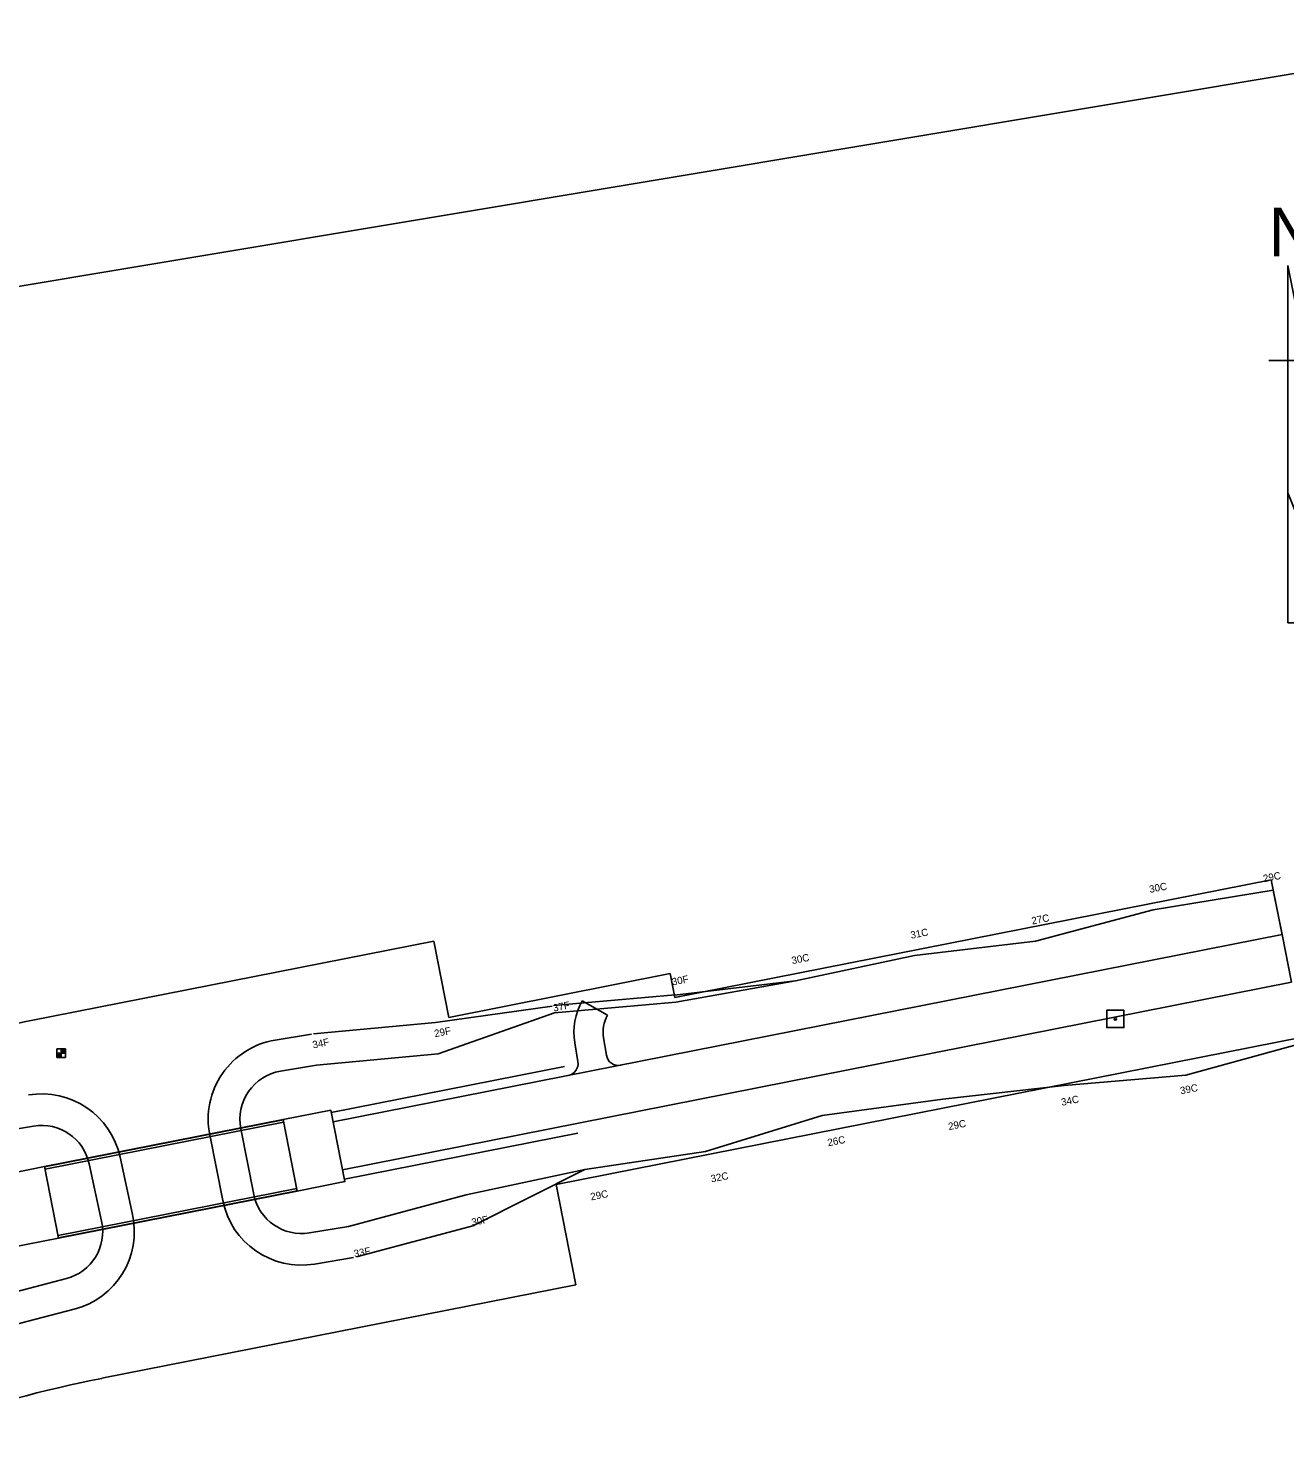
# Model space of a CAD drawing. Extents: x 1509010 to 1513406, y 898655 to 900162.
# Drawn here: x 1510966 to 1511482, y 899577 to 900162 of the extents above; entities that cross this region are included whole.
import ezdxf

# ---------------------------------------------------------------- set-up
doc = ezdxf.new("R2010")
doc.units = 0
for name, color, linetype in [('BR_CONCRETE', 7, 'Continuous'), ('RD_EX_Misc', 7, 'Continuous'), ('RD_HC_Survey', 7, 'Continuous'), ('RD_PD_CstnLmt', 7, 'Continuous'), ('RD_PD_CstnLmt_TX', 7, 'Continuous'), ('RD_PD_DR_ErosCtrl', 7, 'Continuous'), ('RD_PD_Final_TrvlWay', 7, 'Continuous'), ('RD_PD_GR', 7, 'Continuous'), ('RD_PD_RW', 7, 'Continuous'), ('RD_Sketch2', 7, 'Continuous')]:
    doc.layers.add(name, color=color, linetype=linetype)

# ---------------------------------------------------------------- blocks, each defined once
blk = doc.blocks.new('NA')
at = {"layer": 'RD_EX_Misc'}
for p, q in [((7.92, 31.07), (0.08, 70.27)), ((0.08, 70.27), (0.08, 70.27)), ((0.08, 70.27), (0.08, 31.07)), ((-7.76, 31.07), (0.08, 31.07)), ((0.08, -23.33), (0.08, 31.07)), ((0.08, 31.07), (7.92, 31.07)), ((7.92, 31.07), (7.92, 31.54)), ((9.88, -47.33), (0.08, -23.33)), ((0.08, -23.33), (0.08, -76.73)), ((9.88, -76.73), (9.88, -47.06)), ((9.88, -47.06), (9.88, -47.33)), ((0.08, -76.73), (9.88, -76.73))]:
    blk.add_line(p, q, dxfattribs=at)
blk.add_text('N', height=20, dxfattribs=at).set_placement((-7.81, 73.98))

msp = doc.modelspace()

# ---------------------------------------------------------------- linework, layer by layer
at = {"layer": 'BR_CONCRETE'}
for p, q in [((1510972.26, 899694.11), (1511070.36, 899713.48)), ((1510972.45, 899693.13), (1511070.55, 899712.5)), ((1510977.84, 899665.82), (1511075.95, 899685.2)), ((1510978.03, 899664.84), (1511076.14, 899684.22))]:
    msp.add_line(p, q, dxfattribs=at)
for points in [[(1510972.24, 899694.19), (1511070.34, 899713.57), (1511076.16, 899684.13), (1510978.05, 899664.76)], [(1511089.97, 899717.44), (1511070.34, 899713.57), (1511076.16, 899684.13), (1511095.78, 899688.01)], [(1510972.24, 899694.19), (1510952.62, 899690.32), (1510958.43, 899660.89), (1510978.05, 899664.76)]]:
    msp.add_lwpolyline(points, close=True, dxfattribs=at)
at = {"layer": 'RD_HC_Survey'}
for p, q in [((1510979.06, 899742.59), (1510979.06, 899739.09)), ((1510979.08, 899742.59), (1510979.08, 899740.84)), ((1510979.1, 899742.59), (1510979.1, 899740.84)), ((1510979.13, 899742.59), (1510979.13, 899740.84)), ((1510979.15, 899742.59), (1510979.15, 899740.84)), ((1510979.17, 899742.59), (1510979.17, 899740.84)), ((1510979.2, 899742.59), (1510979.2, 899740.84)), ((1510979.22, 899742.59), (1510979.22, 899740.84)), ((1510979.25, 899742.59), (1510979.25, 899740.84)), ((1510979.27, 899742.59), (1510979.27, 899740.84)), ((1510979.3, 899742.59), (1510979.3, 899740.84)), ((1510979.32, 899742.59), (1510979.32, 899740.84)), ((1510979.35, 899742.59), (1510979.35, 899740.84)), ((1510979.37, 899742.59), (1510979.37, 899740.84)), ((1510979.4, 899742.59), (1510979.4, 899740.84)), ((1510979.42, 899742.59), (1510979.42, 899740.84)), ((1510979.45, 899742.59), (1510979.45, 899740.84)), ((1510979.47, 899742.59), (1510979.47, 899740.84)), ((1510979.5, 899742.59), (1510979.5, 899740.84)), ((1510979.52, 899742.59), (1510979.52, 899740.84)), ((1510979.55, 899742.59), (1510979.55, 899740.84)), ((1510979.57, 899742.59), (1510979.57, 899740.84)), ((1510979.6, 899742.59), (1510979.6, 899740.84)), ((1510979.62, 899742.59), (1510979.62, 899740.84)), ((1510979.64, 899742.59), (1510979.64, 899740.84)), ((1510979.67, 899742.59), (1510979.67, 899740.84)), ((1510979.69, 899742.59), (1510979.69, 899740.84)), ((1510979.72, 899742.59), (1510979.72, 899740.84)), ((1510979.74, 899742.59), (1510979.74, 899740.84)), ((1510979.77, 899742.59), (1510979.77, 899740.84)), ((1510979.79, 899742.59), (1510979.79, 899740.84)), ((1510979.82, 899742.59), (1510979.82, 899740.84)), ((1510979.84, 899742.59), (1510979.84, 899740.84)), ((1510979.87, 899742.59), (1510979.87, 899740.84)), ((1510979.89, 899742.59), (1510979.89, 899740.84)), ((1510979.92, 899742.59), (1510979.92, 899740.84)), ((1510979.94, 899742.59), (1510979.94, 899740.84)), ((1510979.97, 899742.59), (1510979.97, 899740.84)), ((1510979.99, 899742.59), (1510979.99, 899740.84)), ((1510980.02, 899742.59), (1510980.02, 899740.84)), ((1510980.04, 899742.59), (1510980.04, 899740.84)), ((1510980.07, 899742.59), (1510980.07, 899740.84)), ((1510980.09, 899742.59), (1510980.09, 899740.84)), ((1510980.12, 899742.59), (1510980.12, 899740.84)), ((1510980.14, 899742.59), (1510980.14, 899740.84)), ((1510980.16, 899742.59), (1510980.16, 899740.84)), ((1510980.19, 899742.59), (1510980.19, 899740.84)), ((1510980.21, 899742.59), (1510980.21, 899740.84)), ((1510980.24, 899742.59), (1510980.24, 899740.84)), ((1510980.26, 899742.59), (1510980.26, 899740.84)), ((1510980.29, 899742.59), (1510980.29, 899740.84)), ((1510980.31, 899742.59), (1510980.31, 899740.84)), ((1510980.34, 899742.59), (1510980.34, 899740.84)), ((1510980.36, 899742.59), (1510980.36, 899740.84)), ((1510980.39, 899742.59), (1510980.39, 899740.84)), ((1510980.41, 899742.59), (1510980.41, 899740.84)), ((1510980.44, 899742.59), (1510980.44, 899740.84)), ((1510980.46, 899742.59), (1510980.46, 899740.84)), ((1510980.49, 899742.59), (1510980.49, 899740.84)), ((1510980.51, 899742.59), (1510980.51, 899740.84)), ((1510980.54, 899742.59), (1510980.54, 899740.84)), ((1510980.56, 899742.59), (1510980.56, 899740.84)), ((1510980.59, 899742.59), (1510980.59, 899740.84)), ((1510980.61, 899742.59), (1510980.61, 899740.84)), ((1510980.63, 899742.59), (1510980.63, 899740.84)), ((1510980.66, 899742.59), (1510980.66, 899740.84)), ((1510980.68, 899742.59), (1510980.68, 899740.84)), ((1510980.71, 899742.59), (1510980.71, 899740.84)), ((1510980.73, 899742.59), (1510980.73, 899740.84)), ((1510980.76, 899742.59), (1510980.76, 899740.84)), ((1510980.78, 899742.59), (1510980.78, 899740.84)), ((1510980.81, 899740.84), (1510977.31, 899740.84)), ((1510977.31, 899740.84), (1510977.31, 899739.09)), ((1510977.33, 899740.84), (1510977.33, 899739.09)), ((1510977.36, 899740.84), (1510977.36, 899739.09)), ((1510977.38, 899740.84), (1510977.38, 899739.09)), ((1510977.41, 899740.84), (1510977.41, 899739.09)), ((1510977.43, 899740.84), (1510977.43, 899739.09)), ((1510977.46, 899740.84), (1510977.46, 899739.09)), ((1510977.48, 899740.84), (1510977.48, 899739.09)), ((1510977.51, 899740.84), (1510977.51, 899739.09)), ((1510977.53, 899740.84), (1510977.53, 899739.09)), ((1510977.56, 899740.84), (1510977.56, 899739.09)), ((1510977.58, 899740.84), (1510977.58, 899739.09)), ((1510977.6, 899740.84), (1510977.6, 899739.09)), ((1510977.63, 899740.84), (1510977.63, 899739.09)), ((1510977.65, 899740.84), (1510977.65, 899739.09)), ((1510977.68, 899740.84), (1510977.68, 899739.09)), ((1510977.7, 899740.84), (1510977.7, 899739.09)), ((1510977.73, 899740.84), (1510977.73, 899739.09)), ((1510977.75, 899740.84), (1510977.75, 899739.09)), ((1510977.78, 899740.84), (1510977.78, 899739.09)), ((1510977.8, 899740.84), (1510977.8, 899739.09)), ((1510977.83, 899740.84), (1510977.83, 899739.09)), ((1510977.85, 899740.84), (1510977.85, 899739.09)), ((1510977.88, 899740.84), (1510977.88, 899739.09)), ((1510977.9, 899740.84), (1510977.9, 899739.09)), ((1510977.93, 899740.84), (1510977.93, 899739.09)), ((1510977.95, 899740.84), (1510977.95, 899739.09)), ((1510977.98, 899740.84), (1510977.98, 899739.09)), ((1510978, 899740.84), (1510978, 899739.09)), ((1510978.03, 899740.84), (1510978.03, 899739.09)), ((1510978.05, 899740.84), (1510978.05, 899739.09)), ((1510978.08, 899740.84), (1510978.08, 899739.09)), ((1510978.1, 899740.84), (1510978.1, 899739.09)), ((1510978.12, 899740.84), (1510978.12, 899739.09)), ((1510978.15, 899740.84), (1510978.15, 899739.09)), ((1510978.17, 899740.84), (1510978.17, 899739.09)), ((1510978.2, 899740.84), (1510978.2, 899739.09)), ((1510978.22, 899740.84), (1510978.22, 899739.09)), ((1510978.25, 899740.84), (1510978.25, 899739.09)), ((1510978.27, 899740.84), (1510978.27, 899739.09)), ((1510978.3, 899740.84), (1510978.3, 899739.09)), ((1510978.32, 899740.84), (1510978.32, 899739.09)), ((1510978.35, 899740.84), (1510978.35, 899739.09)), ((1510978.37, 899740.84), (1510978.37, 899739.09)), ((1510978.4, 899740.84), (1510978.4, 899739.09)), ((1510978.42, 899740.84), (1510978.42, 899739.09)), ((1510978.45, 899740.84), (1510978.45, 899739.09)), ((1510978.47, 899740.84), (1510978.47, 899739.09)), ((1510978.5, 899740.84), (1510978.5, 899739.09)), ((1510978.52, 899740.84), (1510978.52, 899739.09)), ((1510978.55, 899740.84), (1510978.55, 899739.09)), ((1510978.57, 899740.84), (1510978.57, 899739.09)), ((1510978.59, 899740.84), (1510978.59, 899739.09)), ((1510978.62, 899740.84), (1510978.62, 899739.09)), ((1510978.64, 899740.84), (1510978.64, 899739.09)), ((1510978.67, 899740.84), (1510978.67, 899739.09)), ((1510978.69, 899740.84), (1510978.69, 899739.09)), ((1510978.72, 899740.84), (1510978.72, 899739.09)), ((1510978.74, 899740.84), (1510978.74, 899739.09)), ((1510978.77, 899740.84), (1510978.77, 899739.09)), ((1510978.79, 899740.84), (1510978.79, 899739.09)), ((1510978.82, 899740.84), (1510978.82, 899739.09)), ((1510978.84, 899740.84), (1510978.84, 899739.09)), ((1510978.87, 899740.84), (1510978.87, 899739.09)), ((1510978.89, 899740.84), (1510978.89, 899739.09)), ((1510978.92, 899740.84), (1510978.92, 899739.09)), ((1510978.94, 899740.84), (1510978.94, 899739.09)), ((1510978.97, 899740.84), (1510978.97, 899739.09)), ((1510978.99, 899740.84), (1510978.99, 899739.09)), ((1510979.02, 899740.84), (1510979.02, 899739.09)), ((1510979.04, 899740.84), (1510979.04, 899739.09))]:
    msp.add_line(p, q, dxfattribs=at)
for points in [[(1511416.18, 899758.46), (1511409.11, 899758.46), (1511409.11, 899751.39), (1511416.18, 899751.39)], [(1510980.81, 899742.59), (1510977.31, 899742.59), (1510977.31, 899739.09), (1510980.81, 899739.09)]]:
    msp.add_lwpolyline(points, close=True, dxfattribs=at)
msp.add_circle((1511412.65, 899754.92), 0.5, dxfattribs=at)
at = {"layer": 'RD_PD_CstnLmt'}
for p, q in [((1511428.26, 899799.86), (1511477.62, 899807.95)), ((1511477.62, 899807.95), (1511481.25, 899789.61)), ((1511379.86, 899786.86), (1511428.26, 899799.86)), ((1511330.05, 899780.99), (1511379.86, 899786.86)), ((1511281.15, 899770.56), (1511330.05, 899780.99)), ((1511231.92, 899761.78), (1511281.15, 899770.56)), ((1511182.01, 899757.41), (1511231.92, 899761.78)), ((1511134.18, 899740.52), (1511182.01, 899757.41)), ((1511441.69, 899731.84), (1511490.03, 899745.13)), ((1511084.13, 899735.89), (1511069.25, 899733.41)), ((1511084.13, 899735.89), (1511134.18, 899740.52)), ((1511391.59, 899727.48), (1511441.69, 899731.84)), ((1511341.72, 899721.92), (1511391.59, 899727.48)), ((1511292.06, 899715.27), (1511341.72, 899721.92)), ((1511244.03, 899700.41), (1511292.06, 899715.27)), ((1510935.04, 899705.37), (1510967.77, 899710.83)), ((1511058.29, 899682.77), (1511052.93, 899709.79)), ((1511194.53, 899693), (1511244.03, 899700.41)), ((1510995.72, 899671.7), (1510990.61, 899695.33)), ((1511145.63, 899682.52), (1511194.53, 899693)), ((1511097.22, 899669.61), (1511145.63, 899682.52)), ((1511097.22, 899669.61), (1511081.2, 899666.93)), ((1510952.21, 899640.58), (1510981.21, 899648.12))]:
    msp.add_line(p, q, dxfattribs=at)
for centre, start, end in [((1511072.55, 899713.68), 99.47431, 191.2324), ((1510971.06, 899691.1), 12.18941, 99.47431), ((1511077.91, 899686.66), 191.2324, 279.47431), ((1510976.17, 899667.48), 284.5933, 12.18941)]:
    msp.add_arc(centre, 20, start, end, dxfattribs=at)
at = {"layer": 'RD_PD_DR_ErosCtrl'}
for p, q in [((1511231.33, 899764.72), (1511281.15, 899770.56)), ((1511181.75, 899760.4), (1511231.65, 899764.77)), ((1511132.99, 899753.46), (1511181.01, 899760.24)), ((1511082.93, 899748.84), (1511132.99, 899753.46)), ((1511081.99, 899748.72), (1511067.11, 899746.23)), ((1511045.54, 899680.23), (1511040.18, 899707.25)), ((1511008.42, 899674.45), (1511003.32, 899698.07)), ((1511148.36, 899669.81), (1511194.53, 899693)), ((1511100.57, 899657.05), (1511148.99, 899669.96)), ((1511099.36, 899656.78), (1511083.34, 899654.11)), ((1510955.49, 899627.99), (1510984.48, 899635.54))]:
    msp.add_line(p, q, dxfattribs=at)
for centre, start, end in [((1511072.55, 899713.68), 99.47431, 191.2324), ((1510971.06, 899691.1), 12.18941, 99.47431), ((1511077.91, 899686.66), 191.2324, 279.47431), ((1510976.17, 899667.48), 284.5933, 12.18941)]:
    msp.add_arc(centre, 33, start, end, dxfattribs=at)
at = {"layer": 'RD_PD_Final_TrvlWay'}
for p, q in [((1511090.93, 899712.54), (1511481.25, 899789.61)), ((1511485.12, 899769.99), (1511481.25, 899789.61)), ((1511094.81, 899692.91), (1511485.12, 899769.99)), ((1511193.41, 899762.41), (1511203.81, 899756.42)), ((1511203.32, 899739.98), (1511202.13, 899747.12)), ((1511191.59, 899737.36), (1511190.29, 899745.15))]:
    msp.add_line(p, q, dxfattribs=at)
for centre, radius, start, end in [((1511215.94, 899749.43), 26, 150.04166, 189.47431), ((1511215.94, 899749.43), 14, 150.04166, 189.47431), ((1511186.66, 899736.54), 5, 281.17037, 9.47431), ((1511208.25, 899740.8), 5, 189.47431, 281.17037)]:
    msp.add_arc(centre, radius, start, end, dxfattribs=at)
at = {"layer": 'RD_PD_GR'}
for p, q in [((1511090.16, 899716.46), (1511186.16, 899735.42)), ((1511191.58, 899707.95), (1511095.58, 899688.99))]:
    msp.add_line(p, q, dxfattribs=at)
at = {"layer": 'RD_PD_RW'}
for p, q in [((1511231.53, 899763.74), (1511476.79, 899812.17)), ((1511476.79, 899812.17), (1511481.27, 899789.52)), ((1510966.73, 899754.27), (1511132.3, 899786.96)), ((1511132.3, 899786.96), (1511138.5, 899755.57)), ((1511138.5, 899755.57), (1511229.59, 899773.55)), ((1511231.53, 899763.74), (1511229.59, 899773.55)), ((1511182.65, 899686.82), (1511489.58, 899747.42)), ((1511190.79, 899645.61), (1511182.65, 899686.82)), ((1510995.79, 899607.11), (1511190.79, 899645.61))]:
    msp.add_line(p, q, dxfattribs=at)
for radius in [673.54, 523.54]:
    msp.add_arc((1511097.22, 899093.48), radius, 101.17037, 109.15259, dxfattribs=at)
at = {"layer": 'RD_Sketch2'}
msp.add_lwpolyline([(1510176.81, 899925.26), (1511597.17, 900162.3), (1511742.02, 899294.3), (1510321.67, 899057.27)], close=True, dxfattribs=at)

# ---------------------------------------------------------------- block references
at = {"layer": 'RD_Sketch2', "rotation": 4.034374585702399e-11}
msp.add_blockref('NA', (1511483.52, 899994.6), dxfattribs=at)

# ---------------------------------------------------------------- texts
at = {"layer": 'RD_PD_CstnLmt_TX'}
for s, p in [('29C', (1511473.73, 899811.13)), ('30C', (1511426.9, 899806.73)), ('27C', (1511378.5, 899793.72)), ('31C', (1511328.7, 899787.86)), ('30C', (1511279.79, 899777.43)), ('30F', (1511230.56, 899768.65)), ('37F', (1511181.71, 899757.91)), ('34F', (1511082.77, 899742.76)), ('29F', (1511132.83, 899747.39)), ('34C', (1511390.69, 899719.16)), ('39C', (1511439.6, 899723.87)), ('29C', (1511344.23, 899709.17)), ('26C', (1511294.58, 899702.52)), ('32C', (1511246.55, 899687.66)), ('29C', (1511197.05, 899680.25)), ('30F', (1511148.15, 899669.77)), ('33F', (1511099.74, 899656.85))]:
    msp.add_text(s, height=3, rotation=11.17037, dxfattribs=at).set_placement(p)

doc.saveas('drawing.dxf')
